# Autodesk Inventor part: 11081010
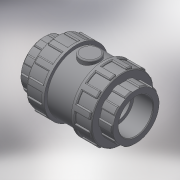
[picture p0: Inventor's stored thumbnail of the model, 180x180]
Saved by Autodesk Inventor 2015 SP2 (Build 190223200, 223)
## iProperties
Created: 2017-11
Part Number: 11081010
Material: Generic
Description: PLASSON CHECK VALVE THR 1" PTFE COATED SPRING + EPDM O-RING
Document SubType Name: Modeling
Designer: KIM
Density: 1 g/cm^3
Appearance: Default
Author: KIM
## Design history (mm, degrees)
derived "110810 - 110610 110910 - 110010.ipt"
feature "Solid1::110810 - 110610 110910 - 110010.ipt"
tag "TaggingFeature1"
body "Solid1"
other parameters: "d0" = 102, "d1" = 30.291, "d2" = 66, "d3" = 22, "d4" = 24.2328, "d5" = 15.4, "d7" = 42.4074, "d8" = 59.4, "d13" = 0.90873, "d23" = 22, "d24" = 63.36, "d25" = 0.60582, "d26" = 0.90873, "d27" = 9.9, "d28" = 4.95, "d29" = 16.5, "d30" = 0, "d35" = 0.90873, "d39" = 33, "d45" = 360 deg, "d47" = 0.60582, "d50" = 33, "d51" = 19.8, "d53" = 0, "d54" = 1.32, "d55" = 6.0582, "d56" = 3.0291, "d58" = 0, "d59" = 0.90873, "d61" = 360 deg, "G_" = 30.291, "l_" = 22, "H_" = 102, "K_" = 66
